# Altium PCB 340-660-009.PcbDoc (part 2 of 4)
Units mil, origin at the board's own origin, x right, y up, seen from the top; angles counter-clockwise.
Board outline 2755.91 x 2755.91 mil, 4 copper layers (Top Layer, Int1 (PWR), Int2 (GND), Bottom Layer), stack 53.912 mil thick; 183 components, 253 nets, 930 pads, 492 vias.
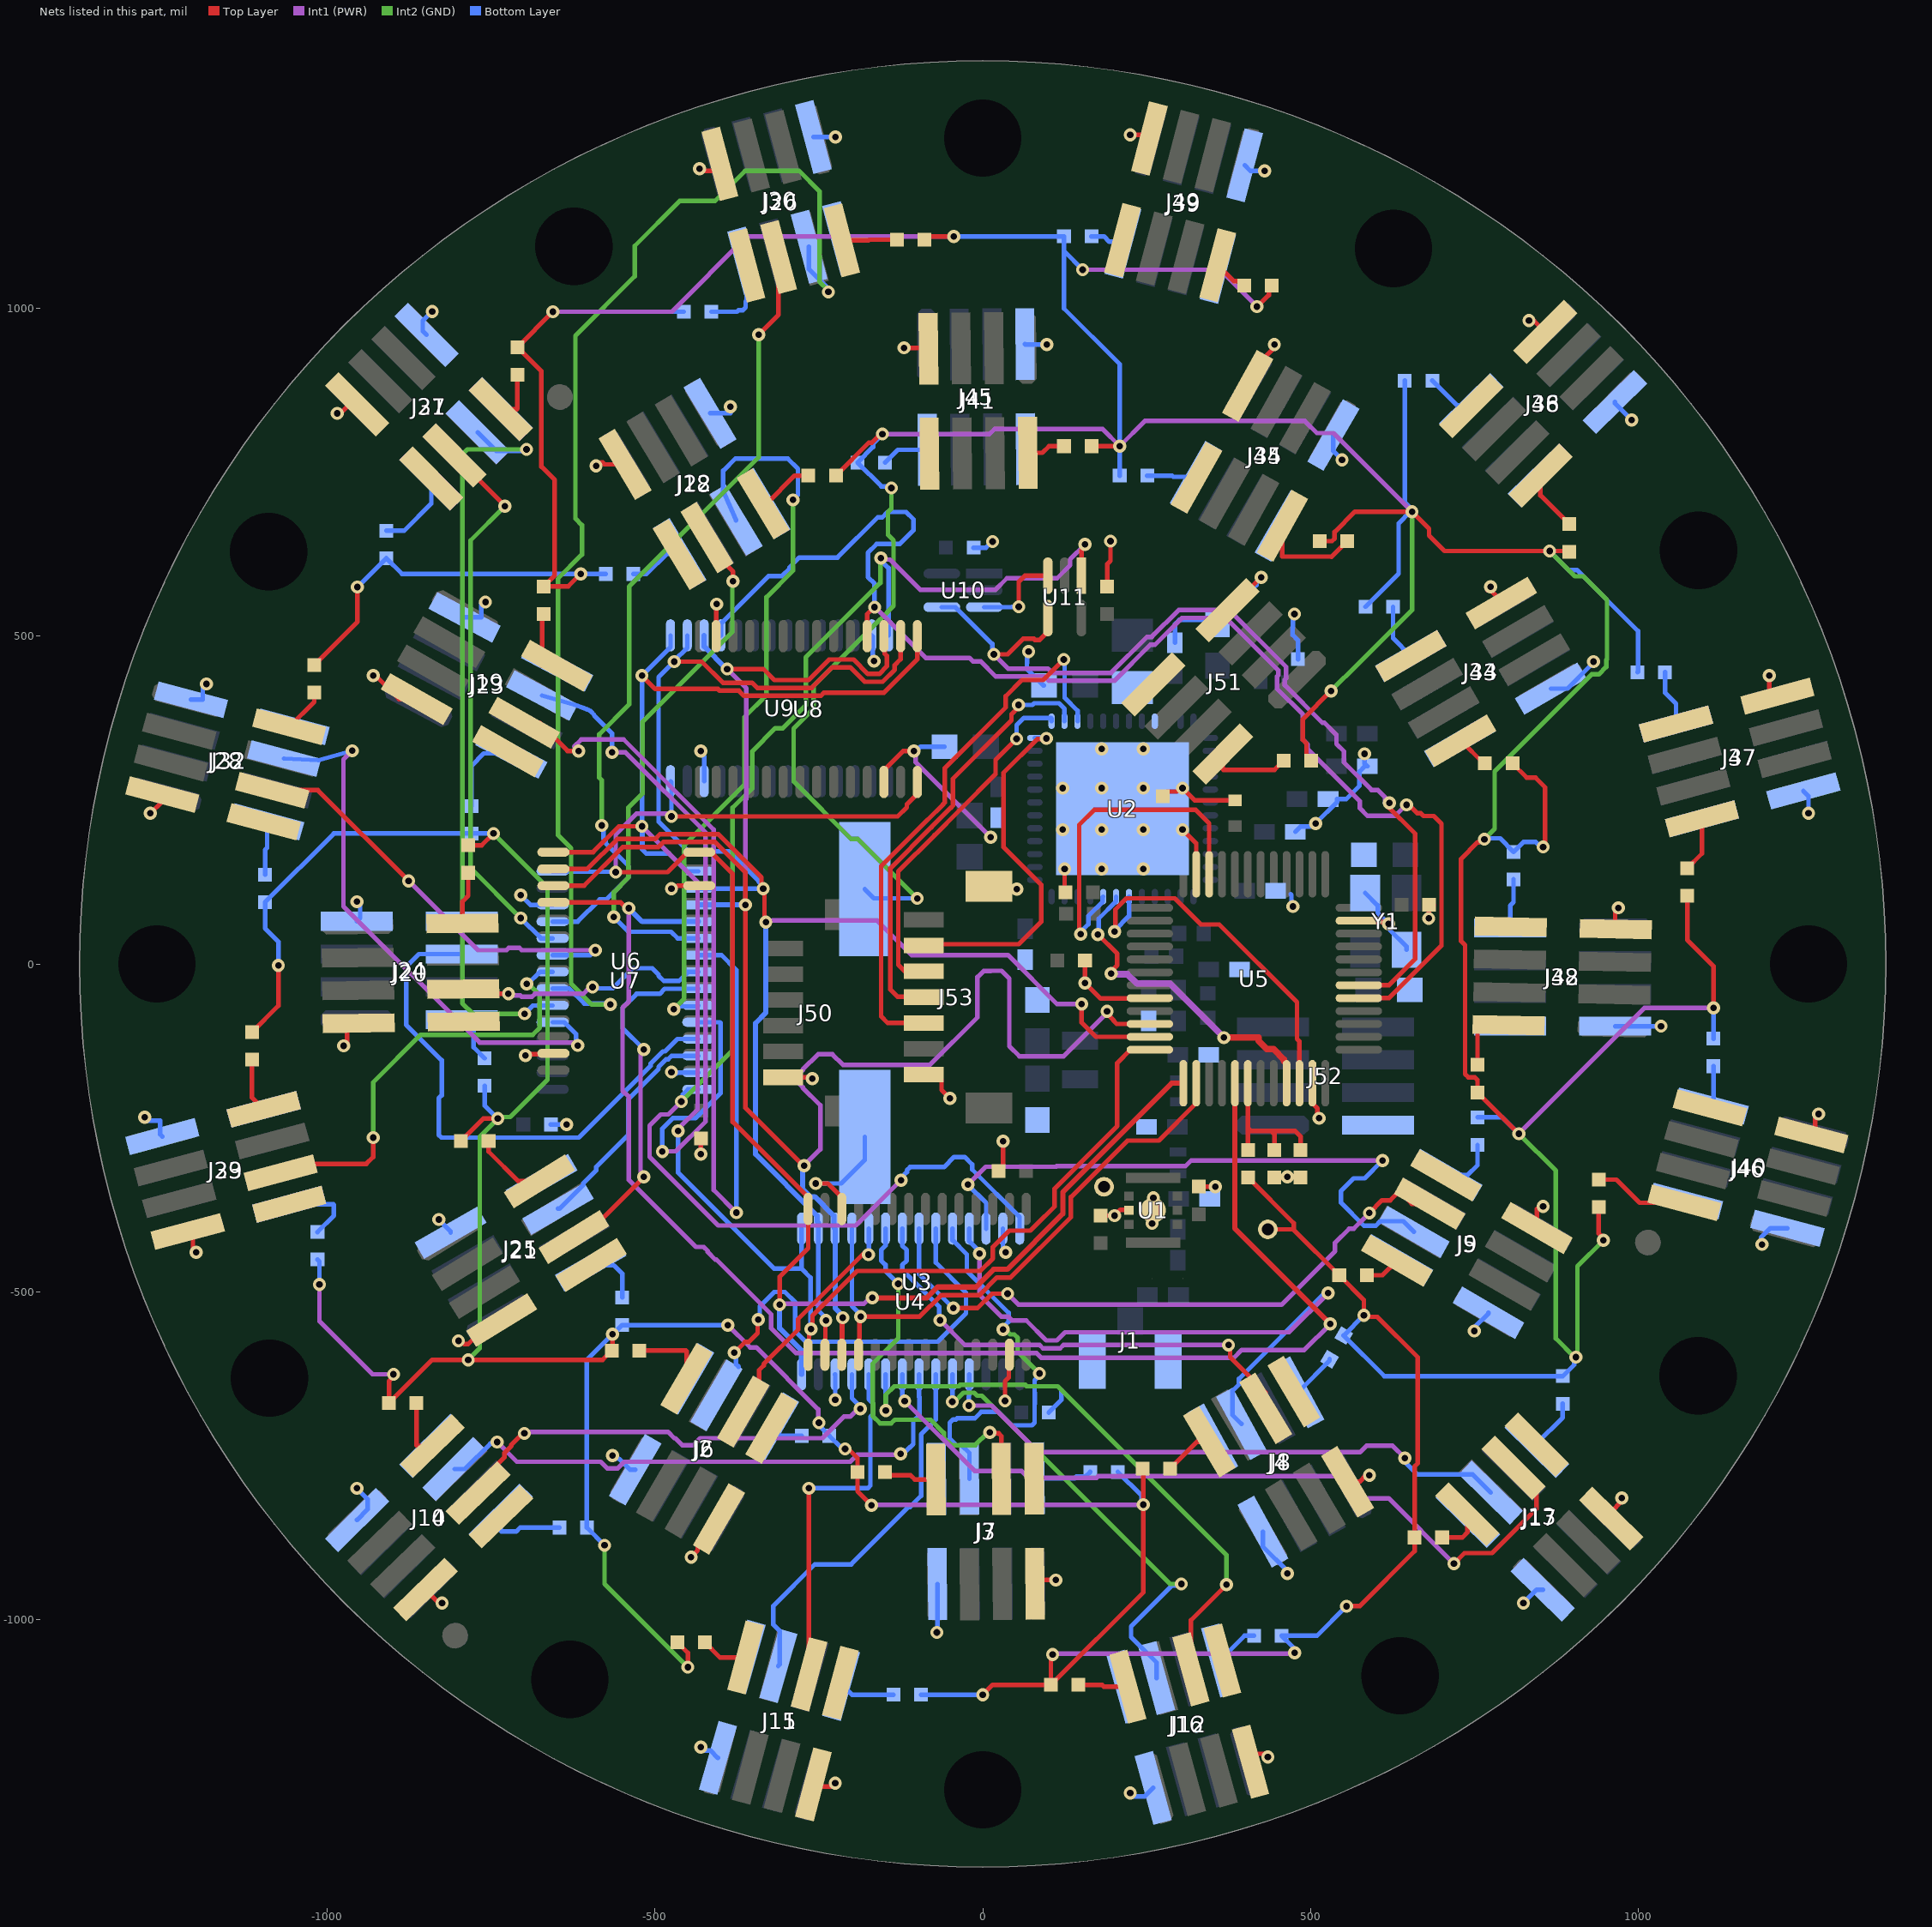
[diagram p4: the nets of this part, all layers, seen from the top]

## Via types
v1: diameter 20, hole 10, Top Layer to Bottom Layer, tented both sides, 489 vias
v2: diameter 20, hole 10, Top Layer to Bottom Layer, 3 vias

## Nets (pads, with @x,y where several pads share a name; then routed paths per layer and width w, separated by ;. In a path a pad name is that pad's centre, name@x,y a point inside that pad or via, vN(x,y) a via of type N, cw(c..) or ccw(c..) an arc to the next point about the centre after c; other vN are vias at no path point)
CTR_A0: U3.17 U4.17 U5.10 U6.17 U7.17 U8.17 U9.17 | length 2948.7
  Top Layer w7: U6.17@-655,119.41 -608.17,119.41 -549.08,178.5 -494.84,178.5 -487.37,185.98 -408.47,185.98 -362.04,139.55 -362.04,-219.54 -273.93,-307.65 v1(-272.65,-307.65) ; v1(-390,450) -334.63,450 -317.72,433.08 -265.87,433.08 -234.38,464.58 -197.14,464.58 -175.09,442.52 -157.73,442.52 -146.31,453.94 -146.31,470.1 -149.57,473.36 -149.57,498.7 U8.17@-150.87,500 ; v1(189.79,-72.26) 189.79,-75.78 199.5,-85.48 199.5,-86.59 204.45,-91.54 U5.10@254.94,-91.54
  Top Layer w8: U3.17@-215.16,-596.22 -214.4,-595.46 -214.4,-540.56 v1(-213.64,-539.8)
  Int1 (PWR) w7: v1(-390,450) -360.6,420.6 -360.6,251.58 -362.04,250.14 v1(-362.04,90.16) ; v1(-272.65,-307.65) -247.81,-282.81 -247.81,-215.6 -274.5,-188.9 -274.5,-188.08 -279.5,-183.08 -279.5,-166.92 -274.5,-161.92 -274.5,-161.1 -251.16,-137.76 -229.5,-137.76 -213.3,-153.96 -80.48,-153.96 -8,-81.48 -8,-20.17 1.29,-10.87 12.17,-10.87 12.54,-10.5 28.69,-10.5 40.5,-22.31 40.5,-125.41 55.91,-140.82 123.53,-140.82 189.79,-74.56 v1(189.79,-72.26)
  Bottom Layer w8: U7.17@-433.78,90.16 v1(-362.04,90.16) ; U9.17@-425.16,501.22 -425.16,484.33 -390.83,450 v1(-390,450) ; v1(-272.65,-307.65) -274.95,-309.95 -274.95,-326.66 -275,-326.72 -275,-343.28 -263.28,-355 -256.22,-355 -227.05,-384.18 -227.05,-401.89 U4.17@-225.16,-403.78 -225.16,-525.03 -213.64,-536.55 v1(-213.64,-539.8)
CTR_A1: U3.16 U4.16 U5.11 U6.16 U7.16 U8.16 U9.16 | length 2869.2
  Top Layer w7: U6.16@-655,145 -603.14,145 -557.64,190.5 -499.82,190.5 -492.34,197.98 -403.5,197.98 -337.49,131.97 -337.49,115.5 -332.97,110.98 -332.97,65.66 v1(-330.94,63.63) ; v1(-470.81,461.29) -428.87,461.29 -396.55,428.97 -351.88,428.97 -343.99,421.08 -260.9,421.08 -229.41,452.58 -202.11,452.58 -180.06,430.52 -152.76,430.52 -134.31,448.97 -134.31,455.86 -125.28,464.89 U8.16@-125.28,500 ; U3.16@-240.75,-596.22 -240.03,-595.5 -240.03,-544.58 v1(-239.32,-543.86) ; v1(151,-61.22) 151,-89.38 172.85,-111.23 U5.11@254.94,-111.23
  Int1 (PWR) w7: v1(-330.94,63.63) -328.45,66.12 -320.6,66.12 -320.34,66.38 -161.38,66.38 -108.5,13.5 38.64,13.5 113.35,-61.22 v1(151,-61.22)
  Bottom Layer w7: U9.16@-450.75,501.22 -450.75,482.43 -470.81,462.37 v1(-470.81,461.29) -494.5,437.6 -494.5,216.92 -449.53,171.96 -387.07,171.96 -342.1,126.99 -342.1,125.62 v1@-333.24,116.76 ; U7.16@-433.78,115.75 -433.03,115 v1(-335,115) ; U4.16@-250.75,-394.92 -250.75,-528.92 -239.32,-540.35 v1(-239.32,-543.86)
  Bottom Layer w8: v1(-330.94,63.63) -330.94,-74.55 -346.65,-90.26 -346.65,-290.16 -252.64,-384.18 -252.64,-393.03 U4.16@-250.75,-394.92
CTR_A2: U3.15 U4.15 U5.12 U6.15 U7.15 U8.15 U9.15 | length 2937.3
  Top Layer w7: U6.15@-655,170.59 -594.52,170.59 -555.11,210 v1(-520,210) ; v1(-520,439.84) -499.66,419.5 -404.05,419.5 -401.52,416.97 -372.02,416.97 -364.13,409.08 -246.99,409.08 -242.5,413.58 -151,413.58 -99.68,464.89 U8.15@-99.68,500 ; U3.15@-266.34,-596.22 -265.04,-594.92 -265.04,-563.33 -259.68,-557.97 -259.68,-536.65 -191.53,-468.5 -3.61,-468.5 15.5,-449.39 15.5,-431.92 40.54,-406.89 72.71,-406.89 81.73,-397.87 109.66,-369.94 109.66,-342.98 205.26,-247.38 205.26,-151.07 225.41,-130.92 U5.12@254.94,-130.92
  Int1 (PWR) w7: v1(-520,210) -435,125 -435,-222.12 -465,-252.12 v1(-465,-255)
  Bottom Layer w7: v1(-520,210) -520,175 -517.5,172.5 ; U9.15@-476.34,501.22 -476.34,483.5 v1(-520,439.84) -520,208.75 -518.75,207.5 -518.75,173.75 -517.5,172.5 ; v1(-465,-255) -465,-318.08 -318.08,-465 -276.34,-465 ; U7.15@-433.78,141.34 -451.5,141.34 -478.66,168.5 -513.5,168.5 -517.5,172.5 ; U4.15@-276.34,-403.78 -276.34,-465 ; v1(-262.16,-556.94) -262.75,-556.36 -262.75,-478.59 -276.34,-465
CTR_A3: U3.14 U4.14 U5.13 U6.14 U7.14 U8.14 U9.14 | length 2542.6
  Top Layer w7: v1(-560,140) -480.87,140 -450.28,170.59 -414.84,170.59 -381.54,137.28 -381.54,-240.87 -266.34,-356.06 -266.34,-433.72 -310,-477.39 v1(-310,-520) ; v1(-475,225) -129.85,225 -115.88,238.98 -115.88,243.65 -99.68,259.84 U8.14@-99.68,277.56
  Top Layer w8: v1(-168.63,-509.44) -85.34,-509.44 -68.9,-493 -10.44,-493 16.59,-465.97 37.31,-465.97 122.16,-381.13 122.16,-348.16 288.22,-182.1 U5.13@306.12,-182.1
  Int1 (PWR) w7: v1(-560,140) -560,197.58 -528.08,229.5 -483.02,229.5 -478.52,225 v1(-475,225) ; v1(-310,-520) -308.44,-518.44 -181.15,-518.44 -172.15,-509.44 v1(-168.63,-509.44)
  Bottom Layer w7: U7.14@-656.22,141.34 -655.55,140.67 -560.67,140.67 v1(-560,140) ; U9.14@-476.34,278.78 -475.04,277.48 -475.04,254.97 -475,254.93 v1(-475,225)
  Bottom Layer w8: v1(-310,-520) -310,-555.95 -276.34,-589.61 U4.14@-276.34,-626.22
CTR_A4: U3.18 U4.18 U5.14 | length 894.4
  Top Layer w7: U3.18@-189.57,-596.22 -188.27,-594.92 -188.27,-539.86 v1(-186.35,-537.94) -96.17,-537.94 -63.72,-505.5 -5.26,-505.5 21.77,-478.47 42.49,-478.47 134.66,-386.3 134.66,-355.7 220.85,-269.5 268.62,-269.5 325.81,-212.31 U5.14@325.81,-182.1
  Bottom Layer w7: U4.18@-199.57,-403.78 -199.57,-522.16 -186.35,-535.38 v1(-186.35,-537.94)
CTR_A5: U5.17 U6.18 U7.18 | length 2300.8
  Top Layer w7: U6.18@-655,93.82 -552.34,93.82 -543.52,85 v1(-540,85)
  Top Layer w8: U5.17@384.86,-182.1 384.86,-403.76 v1(530.4,-549.3)
  Int1 (PWR) w7: v1(-540,85) -540,-57.42 -549.5,-66.92 -549.5,-193.5 -540,-203 -540,-329.58 -437.75,-431.83 -425.75,-431.83 -419.53,-438.05 -419.53,-439.62 -408.11,-451.05 -406.53,-451.05 -322.71,-534.86 -322.71,-556.03 -285.24,-593.5 81.98,-593.5 89.48,-601 383.08,-601 395.08,-589 490.7,-589 v1(530.4,-549.3)
  Bottom Layer w8: v1(-540,85) -519.57,64.57 U7.18@-433.78,64.57
CTR_A6: U5.29 U8.18 U9.18 | length 2117.5
  Top Layer w7: U8.18@-176.46,500 -176.46,533.54 -165.61,544.39 v1(-165,544.39) ; U5.29@573.84,-52.17 619.8,-52.17 700,28.03 700,213.75 688.12,225.63 672.77,225.63 668.22,230.17 662.71,230.17 650.26,242.63 v1(646.74,242.63)
  Int1 (PWR) w7: v1(-165,544.39) -164.39,544.39 -86.94,466.94 -20.42,466.94 -15.13,461.65 -3.1,461.65 19.98,438.57 94.46,438.57 101.09,431.94 200.72,431.94 255.82,487.04 262.99,487.04 303.95,528 371.09,528 451,448.09 451,440.52 449,438.52 449,420.13 488.5,380.64 488.5,342.45 496,334.95 496,327.7 575.2,248.5 575.2,237.89 587.1,225.99 629.43,225.99 646.07,242.63 v1(646.74,242.63)
  Bottom Layer w7: U9.18@-399.57,501.22 -399.57,518.94 -326.68,591.82 -306.18,591.82 -294.76,603.25 -294.76,605.24 -280,620 -221.68,620 -160.29,681.39 -153.2,681.39 -145.09,689.5 -116.92,689.5 -105.5,678.08 -105.5,661.92 -126.78,640.64 -161.89,640.64 -175.06,627.47 -175.06,590.24 -165,580.19 v1(-165,544.39)
CTR_A7: U5.30 U10.4 U11.4 | length 1415.4
  Top Layer w7: v1(17.03,472.32) 38.22,472.32 60.4,494.5 61.92,496 78.08,496 79.62,494.45 86.75,494.45 99.41,507.11 U11.4@99.41,527.71 ; U5.30@573.84,-32.49 619.77,-32.49 660,7.74 660,198.57 616.98,241.58 620.7,245.3 v1(620.7,245.49)
  Int1 (PWR) w7: v1(17.03,472.32) 38.79,450.57 99.43,450.57 106.06,443.94 195.75,443.94 250.85,499.04 258.02,499.04 298.98,540 376.06,540 463,453.06 463,435.55 461,433.55 461,425.1 518.1,368 521.37,368 539.82,349.55 539.82,335.67 551.16,324.33 551.16,307.43 593.13,265.47 602.78,265.47 614.2,254.04 614.2,245.46 614.37,245.3 620.7,245.3 v1(620.7,245.49)
  Bottom Layer w7: U10.4@-62.29,544.41 -41.69,544.41 14.54,488.18 14.54,474.81 v1(17.03,472.32)
DCDC_SW: L2.1 U2.33
DIO1: U2.6 U5.22 | length 571.3
  Top Layer w7: v1(201.31,49.46) 202.47,50.62 202.47,83.05 219.45,100.03 293,100.03 332.76,60.27 360.82,60.27 479.5,-58.41 479.5,-114.5 483.29,-118.29 U5.22@483.29,-182.1
  Bottom Layer w7: v1(201.31,49.46) 201.31,51.26 223.21,73.15 U2.6@223.21,102.68
DIO2: U2.7 U5.21 | length 503.9
  Top Layer w7: v1(175.64,45) 205.2,15.43 205.2,-1.97 195.99,-11.18 v1(195.99,-14.7)
  Top Layer w10: v1(368.03,-112.41) 421.2,-112.41 421.2,-117.59 433.5,-129.89 443.73,-129.89 459.82,-145.98 459.82,-148.3 463.6,-152.08 U5.21@463.6,-182.1
  Int1 (PWR) w10: v1(195.99,-14.7) 197.07,-15.78 220.99,-15.78 235.2,-30 285.62,-30 v1(368.03,-112.41)
  Bottom Layer w7: v1(175.64,45) 176.93,46.3 176.93,69 203.52,95.59 U2.7@203.52,102.68
DIO3: U2.8 U5.46 | length 532.9
  Top Layer w7: v1(149.64,45.5) 147.27,47.87 147.27,212.27 170,235 325,235 345.49,214.51 U5.46@345.49,136.8
  Bottom Layer w7: v1(149.64,45.5) 149.64,49.02 161.29,60.66 161.29,73.04 183.04,94.79 183.04,101.88 U2.8@183.84,102.68
ENB_1: J2.8
ENB_2: J3.8
ENB_3: J4.8
ENB_4: J5.8
ENB_5: J6.8
ENB_6: J7.8
ENB_7: J8.8
ENB_8: J9.8
ENB_9: J10.8
ENB_10: J11.8
ENB_11: J12.8
ENB_12: J13.8
ENB_13: J14.8
ENB_14: J15.8
ENB_15: J16.8
ENB_16: J17.8
ENB_17: J18.8
ENB_18: J19.8
ENB_19: J20.8
ENB_20: J21.8
ENB_21: J22.8
ENB_22: J23.8
ENB_23: J24.8
ENB_24: J25.8
ENB_25: J26.8
ENB_26: J27.8
ENB_27: J28.8
ENB_28: J29.8
ENB_29: J30.8
ENB_30: J31.8
ENB_31: J32.8
ENB_32: J33.8
ENB_33: J34.8
ENB_34: J35.8
ENB_35: J36.8
ENB_36: J37.8
ENB_37: J38.8
ENB_38: J39.8
ENB_39: J40.8
ENB_40: J41.8
ENB_41: J42.8
ENB_42: J43.8
ENB_43: J44.8
ENB_44: J45.8
ENB_45: J46.8
ENB_46: J47.8
ENB_47: J48.8
ENB_48: J49.8
ENB_49: J51.8
ENBL_TIA: U4.28 U7.28 U9.28 U11.1 | length 2365.6
  Top Layer w7: U11.1@150.59,592.29 150.59,631.07 156,636.48 v1(156,640)
  Int1 (PWR) w7: v1(-460,-210) -479.59,-229.59 -491.23,-229.59 -508.33,-246.69 -508.33,-294.4 -403.73,-399 -193.63,-399 v1(-124.63,-330) ; v1(-155.56,619.39) -153.07,616.91 -141.45,616.91 -95.54,571 19.48,571 36.98,588.5 113.5,588.5 133.51,608.51 133.51,617.51 v1(156,640)
  Int2 (GND) w7: v1(-460,-210) -381.54,-131.54 -381.54,238.46 -351.5,268.5 -351.5,324.58 -316.46,359.61 -305.04,359.61 -270,394.65 -270,467.58 -156.16,581.42 -156.16,618.79 v1(-155.56,619.39)
  Bottom Layer w7: v1(-460,-210) -457.51,-207.51 -457.51,-199.19 -449.66,-191.34 U7.28@-433.78,-191.34 ; v1(-155.56,619.39) -155.56,615.88 -143.66,603.98 U9.28@-143.66,501.22 ; v1(-124.63,-330) -124.63,-326.48 -115.64,-317.49 -115.64,-314.95 -110.69,-310 -58.97,-310 -43.58,-294.61 -27.42,-294.61 -16,-306.03 -16,-313.72 56.34,-386.06 U4.28@56.34,-403.78
GND: C1.1 C2.1 C3.- C5.2 C6.2 C7.2 C8.2 C9.2 C10.2 C11.2 C12.2 C14.1 C16.2 C17.2 C18.2 C20.1 C21.1 C22.2 C23.2 C24.2 C25.1 C26.1 C27.1 C28.1 C29.1 C30.1 C31.1 C32.1 C33.1 C34.1 C35.1 C36.1 C37.1 J1.1 J1.2 J2.7 J3.7 J4.7 J5.7 J6.7 J7.7 J8.7 J9.7 J10.7 J11.7 J12.7 J13.7 J14.7 J15.7 J16.7 J17.7 J18.7 J19.7 J20.7 J21.7 J22.7 J23.7 J24.7 J25.7 J26.7 J27.7 J28.7 J29.7 J30.7 J31.7 J32.7 J33.7 J34.7 J35.7 J36.7 J37.7 J38.7 J39.7 J40.7 J41.7 J42.7 J43.7 J44.7 J45.7 J46.7 J47.7 J48.7 J49.7 J50.6 J51.7 J52.2 J53.7 J53.9 R2.1 R53.2 R55.1 TP2.1 U1.2 U1.9 U2.49 U3.12 U3.27 U4.12 U4.27 U5.8 U5.23 U5.35 U5.47 U6.12 U6.27 U7.12 U7.27 U8.12 U8.27 U9.12 U9.27 U10.3 U11.3 Y1.2 Y1.4 | length 5035.8
  Top Layer w7: v1(-1270,230) -1251.78,248.22 J28.7@-1251.78,258.25 ; J29.7@-1212.96,-408.19 -1205,-416.15 -1205,-435.9 -1200.9,-440 v1(-1200,-440) ; v1(-985,840) -980,840 -966.25,853.75 J27.7@-954.68,853.75 ; v1(-975,-125) -974.1,-125 -970,-120.9 -970,-102.27 -958.18,-90.45 J20.7@-952.1,-90.45 ; v1(-930,439.96) -926.48,439.96 -890.62,404.1 J19.7@-863.6,404.1 ; J10.7@-850.41,-954.61 -830.02,-975 v1(-825,-975) ; v1(-800,-575) -796.48,-575 -791.48,-580 -785,-580 -748.33,-543.33 J21.7@-733.93,-543.33 ; v1(-697.79,-139.5) -696.08,-137.79 -656.3,-137.79 U6.27@-655,-136.5 ; v1(-590,760) -587.91,760 -582.73,765.18 -580.18,765.18 -577.14,762.14 J18.7@-545.86,762.14 ; v1(-475,115) -470,115 -465.59,119.41 U6.12@-432.56,119.41 ; v1(-445,-905) -435,-895 -435,-890 -402.39,-857.39 J2.7@-402.39,-846.78 ; v1(-432.17,1213.08) -429.09,1210 -411.55,1210 J26.7@-400.92,1220.63 ; v1(-430,-290) C33.1@-430,-266 ; U8.27@-406.77,500 -406.77,548.17 v1(-405.94,549) ; J50.6@-304.41,-173.03 -261.97,-173.03 v1(-260,-175) ; J11.7@-258.12,-1251.71 -254.83,-1255 -229.1,-1255 -225,-1250.9 v1(-225,-1250) ; v1(-255,-335) -236.22,-335 -215.16,-356.06 U3.12@-215.16,-373.78 ; U8.12@-150.87,277.56 -150.87,295.28 -121.14,325 v1(-105,325) ; v1(-120,940) -84.15,940 J41.7@-82.74,938.6 ; J53.7@-89.88,-168.81 -71.18,-168.81 -62.87,-177.12 -62.87,-192.13 v2(-50,-205) ; C31.1@24,-316.27 31,-309.27 v2(31,-270.5) ; v1@35,-660 35,-665.65 v1(34.06,-666.58) 34.06,-636.84 40,-630.9 40,-596.97 U3.27@40.75,-596.22 ; v1(55,545) 55,583.19 64.1,592.29 U11.3@99.41,592.29 ; J3.7@79.62,-945.76 85.38,-940 v1(111.37,-939.99) ; C27.1@124.4,115.43 125,116.03 v1(125,145) ; C29.1@156,5 156,-29.08 v1(156.17,-29.25) 156.57,-29.25 180.08,-52.76 254.36,-52.76 U5.8@254.94,-52.17 ; C1.1@180,-384 v1(201,-384) 210,-375 222.3,-375 U1.2@223.09,-375.79 ; C36.1@190,576 190,607.1 190,610 195,615 v1(195,645) ; v1(225,1265) 248.63,1265 J49.7@254.3,1259.34 ; C26.1@275,256 282,263 296.21,263 301.38,268.17 v1(304.9,268.17) 323.39,249.69 R53.2@385,249.69 ; v1(304.9,204.9) 325.81,184 U5.47@325.81,136.8 ; C2.1@332.26,-340 v1(355,-340) ; J51.7@373.62,539.69 410.51,575.51 v1(424.76,589.76) ; J35.7@404.35,881.78 404.35,899.35 445,940 v1(445,945) ; J12.7@408.68,-1217.16 420.84,-1205 430.9,-1205 435,-1209.1 v1(435,-1210) ; R55.1@445,-326 464,-326 v1(465,-325) 484,-325 C30.1@485,-326 ; U5.23@502.97,-182.1 502.97,-212.93 510.73,-220.68 510.73,-232.93 v1(513.21,-235.42) ; J4.7@556.58,-790.11 574.89,-790.11 585,-780 v1(590,-780) ; U5.35@573.84,65.94 574.76,65.02 608.09,65.02 609.29,63.82 616.76,63.82 v1(619.25,61.34) ; v1(680.5,69.49) 680.5,83 687.5,90 C28.1@688,90 ; v1@770,570 774.76,574.76 v1(774.76,575.42) 774.76,570.24 791.36,553.64 J34.7@791.36,550.74 ; v1(833.41,981.62) 833.49,981.71 840.88,981.71 J48.7@858.25,964.34 ; J5.7@845.68,-402.84 845.68,-374.1 850.9,-374.1 v1(855,-370) ; J13.7@958.91,-846.31 958.91,-836.09 975,-820 v1(975,-815) ; J38.7@965.9,53.15 965,54.06 965,81.18 969.38,85.57 v1(970,85.57) ; v1(1200,440) 1200,421 J47.7@1212.58,408.43 ; J46.7@1264.31,-261.19 1270,-255.5 1270,-234.1 1275.12,-228.98 v1(1275.27,-228.98)
  Int1 (PWR) w7: v1(-105,325) -102.51,322.51 -102.51,307.88 v1(12.18,193.19)
  Bottom Layer w7: v1(-1278.5,-233.93) -1278.5,-234.59 -1273.99,-239.1 -1255,-239.1 -1255,-260.09 J33.7@-1251.8,-263.29 ; J32.7@-1208.01,403.16 -1190,403.16 -1190,430 -1185,430 -1185,427.73 v1(-1184.42,427.15) ; J24.7@-955.12,65 -950,70.12 -950,90.9 -954.1,95 v1(-955,95) ; v1(-955,-800) -938.57,-816.43 -938.57,-832.25 J14.7@-954.69,-848.38 ; J31.7@-848.62,959.69 -854.39,965.46 -854.39,981.11 v1(-840,995.5) ; v1(-830,-390) -811.88,-408.12 J25.7@-811.88,-410.11 ; J23.7@-790.55,528.83 -765,528.83 -765,550 -760,550 -760,550.93 v1(-758.76,552.17) ; v1(-705,105) -690.16,90.16 U7.12@-656.22,90.16 ; C34.1@-659,-245 v1(-635,-245) ; v1(-565,-750) -561.48,-750 -556.48,-755 -555,-755 -538.44,-771.56 J6.7@-530.11,-771.56 ; v1(-475,-165) -472.9,-167.1 -467.1,-167.1 -465.75,-165.75 U7.27@-433.78,-165.75 ; v1(-430,-1195) -430,-1200 -415.53,-1200 J15.7@-404.16,-1211.37 ; v1(-430,325) -430,321.48 -425,316.48 -425,278.94 U9.12@-425.16,278.78 ; J22.7@-415.91,840.15 -385,840.15 v1(-385,850) ; J30.7@-258.29,1261.8 -220,1261.8 -220,1260 -222.83,1260 v1(-224.59,1261.76) ; v1(-255,-335) -215.87,-335 -180,-299.13 C3.-@-180,-263.98 ; U4.12@-225.16,-626.22 -225,-626.38 v1(-225,-665) ; U9.27@-169.25,501.22 -167.95,499.92 -167.95,464.17 v1(-165.81,462.02) ; v1(-105,325) -101.48,325 -94.95,331.54 C21.1@-58.13,331.54 ; v1(-70,-1020) -69.16,-1019.16 J7.7@-69.16,-946.13 ; C35.1@-14,635 4.89,635 14.39,644.5 v1(15,644.5) ; U10.3@2.29,544.41 44.41,544.41 45,545 v1(55,545) ; U4.27@30.75,-403.78 30.75,-435.9 34.85,-440 v1(35,-440) ; J45.7@64.5,945.59 65.08,945 v1@97.75,945 ; v1(70,476.5) 67.51,474.01 67.51,459.59 67.42,459.5 67.42,450.1 92.52,425 C10.2@93.5,425 ; C32.1@100.76,-684.47 120,-665.23 120,-650 ; v1(225,-1265) 225,-1265.9 229.1,-1270 247.2,-1270 J16.7@259.95,-1257.25 ; C9.2@293.37,490.16 293.37,518.37 300,525 343.17,525 C8.2@358.37,518.03 ; C8.2@358.37,519.02 417.51,578.16 417.51,582.51 v1(424.76,589.76) ; J39.7@399.65,1218.6 408.25,1210 v1(430,1210) ; J8.7@427.55,-866.26 427.55,-889.03 465,-926.48 v1(465,-930) ; 469.74,106.54 470.96,105.32 470.96,90.19 v1(473.44,87.7) ; v1(475.69,533.86) 473.21,531.37 473.21,513.85 472.9,513.55 472.9,502.1 481,494 C20.1@481,465 ; C11.2@476.99,201.54 485.3,209.85 500,209.85 504.53,214.38 v1(508.05,214.38) 540.82,247.15 540.82,251.54 554.64,251.54 574.74,271.63 574.74,293.22 583.05,301.54 R2.1@586.99,301.54 582.66,305.86 v1(582.66,320.48) ; J44.7@535.01,806.88 535.01,782.41 v1(548.27,769.15) ; Y1.2@583.5,108.31 602.64,89.17 602.64,77.94 621.74,58.85 621.74,51.37 646.5,26.61 Y1.4@646.5,21.69 ; v1(750,-560) 750,-555 771.76,-533.24 J9.7@771.76,-532.18 ; v1(825,-975) 845.35,-954.65 J17.7@854.56,-954.65 ; J43.7@866.88,420.11 892.31,420.11 927.2,455 927.83,455 931.93,459.1 v1(931.93,461.23) 930.7,460 v1@930,460 ; J36.7@964.72,857.48 964.72,855.28 v1(990,830) ; J42.7@965.12,-95 v1(1035,-95) ; v1(1189.2,-427.98) 1187.5,-426.27 1187.5,-417.5 1201.78,-403.22 J40.7@1227.91,-403.22 ; J37.7@1252.13,263.92 1260,256.05 v1(1260,230)
  other v1: 258.5,-395.94 260.38,-356.92 52.02,114.03 181.73,145 245,145 121.83,204.9 181.73,204.9 245,204.9 121.83,268.17 181.73,268.17 245,268.17 181.73,328.07 245,328.07 97.77,945.03
HARV_1: J2.2 R4.1 | length 114.4
  Top Layer w7: R4.1@-524,-590 -452.93,-590 -451.93,-591 J2.2@-451.93,-632.96
HARV_2: J3.2 R5.1 | length 82.3
  Top Layer w7: R5.1@-149,-775 -143.78,-780.22 -110.13,-780.22 -103.73,-786.62 J3.2@-71.54,-786.62
HARV_3: J4.2 R6.1 | length 76.7
  Top Layer w7: R6.1@286,-770 326.94,-729.06 J4.2@345.75,-729.06
HARV_4: J5.2 R7.1 | length 55.5
  Top Layer w7: R7.1@586,-475 610,-475 631.9,-453.1 J5.2@631.9,-452.56
HARV_5: J6.2 R8.1 | length 48.7
  Bottom Layer w7: J6.2@-319.89,-708.44 -308.33,-720 R8.1@-276,-720
HARV_6: J7.2 R9.1 | length 88.4
  Bottom Layer w7: J7.2@79.67,-784.8 140.27,-784.8 143.08,-782 157,-782 R9.1@164,-775
HARV_7: J8.2 R10.1 | length 70.1
  Bottom Layer w7: J8.2@482.45,-653.74 482.45,-652 529.27,-605.18 R10.1@529.27,-603.05
HARV_8: J9.2 R11.1 | length 84.4
  Bottom Layer w7: J9.2@707.99,-322.15 740,-322.15 755,-307.15 R11.1@755,-276
HARV_9: J10.2 R12.1 | length 89.2
  Top Layer w7: R12.1@-864,-670 -864,-734.39 -863,-735.39 J10.2@-839.6,-735.39
HARV_10: J11.2 R13.1 | length 71.8
  Top Layer w7: R13.1@-424,-1035 -400.71,-1058.29 J11.2@-361.87,-1058.29
HARV_11: J12.2 R14.1 | length 76.5
  Top Layer w7: R14.1@146,-1100 182,-1100 184.84,-1102.84 J12.2@221.32,-1102.84
HARV_12: J13.2 R15.1 | length 69.3
  Top Layer w7: R15.1@701,-875 732,-875 739.52,-867.48 J13.2@739.52,-839.79
HARV_13: J14.2 R16.1 | length 115.6
  Bottom Layer w7: J14.2@-735.31,-841.62 -735.31,-865 -734.31,-866 -712,-866 -706,-860 R16.1@-646,-860
HARV_14: J15.2 R17.1 | length 86.6
  Bottom Layer w7: J15.2@-215.84,-1098.63 -199.47,-1115 R17.1@-136,-1115
HARV_15: J16.2 R18.1 | length 68
  Bottom Layer w7: J16.2@361.68,-1062.75 399.43,-1025 R18.1@414,-1025
HARV_16: J17.2 R19.1 | length 80.7
  Bottom Layer w7: J17.2@845.44,-735.35 845.44,-731.56 885,-692 R19.1@885,-671
HARV_17: J18.2 R20.1 | length 86.5
  Top Layer w7: J18.2@-334.75,702.05 -329.95,702.05 -287,745 R20.1@-266,745
HARV_18: J19.2 R21.1 | length 103.3
  Top Layer w7: R21.1@-670,534 -670,531.61 -672.11,531.61 -672.11,454.9 J19.2@-650.07,454.9
HARV_19: J20.2 R22.1 | length 81
  Top Layer w7: J20.2@-793.95,61.75 -793.95,95 -785,103.95 R22.1@-785,139
HARV_20: J21.2 R23.1 | length 112.7
  Top Layer w7: R23.1@-754,-270 -754,-286.19 -708.65,-331.54 J21.2@-676.29,-331.54
HARV_21: J22.2 R24.1 | length 83.4
  Bottom Layer w7: R24.1@-533,595 -513,595 -482.4,625.6 J22.2@-462.24,625.6
HARV_22: J23.2 R25.1 | length 129.8
  Bottom Layer w7: R25.1@-780,241 -780,302.5 -761.33,321.17 J23.2@-719.45,321.17
HARV_23: J24.2 R26.1 | length 77.5
  Bottom Layer w7: J24.2@-794.88,-85 -787.97,-85 -776.9,-96.07 -776.9,-127.1 R26.1@-760,-144
HARV_24: J25.2 R27.1 | length 89.8
  Bottom Layer w7: J25.2@-598.12,-459.89 -562.61,-459.89 -550,-472.5 R27.1@-550,-509
HARV_25: J26.2 R28.1 | length 84.3
  Top Layer w7: J26.2@-214.9,1104.14 -174,1104.14 -173.14,1105 R28.1@-131,1105
HARV_26: J27.2 R29.1 | length 77.5
  Top Layer w7: J27.2@-735.32,846.24 -711,846.24 -710,847.24 R29.1@-710,899
HARV_27: J28.2 R30.1 | length 68.1
  Top Layer w7: J28.2@-1058.22,361.75 -1020,399.97 R30.1@-1020,414
HARV_28: J29.2 R31.1 | length 83.3
  Top Layer w7: R31.1@-1115,-146 -1115,-203.85 J29.2@-1097.04,-221.81
HARV_29: J30.2 R32.1 | length 123
  Bottom Layer w7: R32.1@-414,995 -375.09,995 -372.6,997.48 -365.81,997.48 -361.71,1001.58 -361.71,1010.78 -360.11,1012.37 -360.11,1066.61 J30.2@-361.71,1068.2
HARV_30: J31.2 R33.1 | length 123.6
  Bottom Layer w7: R33.1@-910,661 -882.88,661 -841.38,702.5 J31.2@-841.38,740.31
HARV_31: J32.2 R34.1 | length 82.1
  Bottom Layer w7: R34.1@-1095,136 -1095,174 -1091.99,177.01 J32.2@-1091.99,216.84
HARV_32: J33.2 R35.1 | length 120.3
  Bottom Layer w7: J33.2@-1058.2,-366.71 -991,-366.71 -990,-367.71 -990,-384 R35.1@-1015,-409
HARV_33: J34.2 R36.1 | length 51.6
  Top Layer w7: J34.2@728.95,340.31 730,340.31 764.43,305.88 R36.1@766.33,305.88
HARV_34: J35.2 R37.1 | length 155.5
  Top Layer w7: J35.2@457.16,668.74 457.16,622 532,621 R37.1@556,645
HARV_35: J36.2 R38.1 | length 74.8
  Bottom Layer w7: R38.1@686,890 723.49,852.51 J36.2@745.28,852.51
HARV_36: J37.2 R39.1 | length 85.9
  Bottom Layer w7: R39.1@1041,445 1041,413.87 1057.87,397 J37.2@1057.87,366.08
HARV_37: J38.2 R40.1 | length 108.1
  Top Layer w7: R40.1@755,-154 755,-93.32 J38.2@802.44,-93.32
HARV_38: J39.2 R41.1 | length 51.1
  Bottom Layer w7: R41.1@166,1110 185,1110 193.12,1101.88 J39.2@213.77,1101.88
HARV_39: J40.2 R42.1 | length 62
  Bottom Layer w7: J40.2@1112.09,-216.78 1115,-213.87 R42.1@1115,-156
HARV_40: J41.2 R43.1 | length 59.5
  Top Layer w7: J41.2@68.72,779.74 91,779.74 101.26,790 R43.1@124,790
HARV_41: J42.2 R44.1 | length 76.1
  Bottom Layer w7: J42.2@804.88,55 804.88,89 810,94.12 R44.1@810,129
HARV_42: J43.2 R45.1 | length 86.3
  Bottom Layer w7: R45.1@626,545 626,497.01 J43.2@653.12,469.89
HARV_43: J44.2 R46.1 | length 74.8
  Bottom Layer w7: R46.1@251,745 288.88,745 290.77,743.12 J44.2@324.99,743.12
HARV_44: J45.2 R47.1 | length 72.5
  Bottom Layer w7: R47.1@-149,765 -129.59,784.41 J45.2@-84.5,784.41
HARV_45: J46.2 R48.1 | length 145.3
  Top Layer w7: R48.1@940,-329 967.01,-329 1002.48,-364.46 J46.2@1070.64,-364.46
HARV_46: J47.2 R49.1 | length 84.9
  Top Layer w7: R49.1@1075,146 1097.42,168.42 J47.2@1097.42,221.57
HARV_47: J48.2 R50.1 | length 92.2
  Top Layer w7: J48.2@851.05,744.97 851.05,714.95 R50.1@895,671
HARV_48: J49.2 R51.1 | length 53.4
  Top Layer w7: J49.2@358.52,1066.17 382.68,1042 392,1042 R51.1@399,1035
HARV_49: J51.2 R56.1 | length 122.1
  Top Layer w7: J51.2@366.38,320.31 366.38,297 367.38,296 445,296 R56.1@459,310
HARV_IN: C3.+ R4.2 R5.2 R6.2 R7.2 R8.2 R9.2 R10.2 R11.2 R12.2 R13.2 R14.2 R15.2 R16.2 R17.2 R18.2 R19.2 R20.2 R21.2 R22.2 R23.2 R24.2 R25.2 R26.2 R27.2 R28.2 R29.2 R30.2 R31.2 R32.2 R33.2 R34.2 R35.2 R36.2 R37.2 R38.2 R39.2 R40.2 R41.2 R42.2 R43.2 R44.2 R45.2 R46.2 R47.2 R48.2 R49.2 R50.2 R51.2 R54.2 R56.2 TP1.1 | length 15654.6
  Top Layer w7: R31.2@-1115,-104 -1074.79,-63.79 v1(-1074.79,-2.21) ; R30.2@-1020,456 -954,522 v1(-954,575) ; v1(-899,-626) -899,-629.52 -906,-636.52 R12.2@-906,-670 -840,-604 v1(-785,-604) -580,-604 -565,-589 v1(-565,-565) ; R23.2@-796,-270 -762,-236 v1(-740,-236) ; R22.2@-785,181 -764.5,181 v1(-746.5,199) ; v1(-656,995) R29.2@-710,941 -673.32,904.32 -673.32,758.72 -653.1,738.5 -653.1,592.9 R21.2@-670,576 -632.5,576 v1(-613.5,595) ; R13.2@-466,-1035 -450,-1051 v1(-450,-1073) ; R20.2@-224,745 -173.72,795.28 -168.77,795.28 -155.55,808.5 v1(-153,808.5) ; v1(-210,-740) -207.51,-742.49 -202.51,-742.49 -191,-754 R5.2@-191,-775 -191,-804.69 v1(-169.88,-825.81) ; R28.2@-89,1105 -84,1110 v1(-44,1110) ; v1(0,-1115) 15,-1100 R14.2@104,-1100 ; v1(106.58,-1053.58) 106.58,-1057.09 104,-1059.67 R14.2@104,-1100 ; R43.2@166,790 v1(209,790) ; v1@244,-824 245,-823 245,-771 R6.2@244,-770 ; v1(245,-825) 245,-959 R14.2@104,-1100 ; R54.2@405,-326 474.5,-395.5 474.5,-405.5 ; v1(418.5,1003) 435.5,1020 436.9,1020 436.9,1030.9 R51.2@441,1035 ; TP1.1@435,-405 474,-405 474.5,-405.5 ; R56.2@501,310 494,317 494,336.42 488.5,341.92 488.5,373.5 v1(531.5,416.5) ; R37.2@514,645 532.9,645 537,649.1 537,659.02 567.98,690 v1(655,690) 681.09,663.91 681.09,653.6 704.69,630 v1(865,630) ; v1(555,-980) 555.5,-979.5 575.5,-979.5 659,-896 R15.2@659,-875 659,-766.79 663.72,-762.08 663.72,-600.14 602.07,-538.49 584.17,-538.49 v1(581.68,-536) 581.68,-512.68 R7.2@544,-475 474.5,-405.5 ; v1(765.38,190.27) 761.86,190.27 757.12,185.53 755.13,185.53 729.98,160.37 729.98,34.79 736,28.77 736,-168.02 740.98,-173 750.9,-173 755,-177.1 R40.2@755,-196 v1(818,-259) ; R36.2@808.33,305.88 830,284.22 843.39,284.22 858.06,269.56 858.06,185.07 855,182.02 v1(855,178.5) ; v1@866,629 867,630 894,630 R50.2@895,629 ; R48.2@940,-371 940,-411.29 947,-418.29 v1(947,-421.81) ; R49.2@1075,104 1075,36.76 1115,-3.24 v1(1115,-67)
  Int1 (PWR) w7: v1(-1012,-489) -1012,-545.08 -931.08,-626 v1(-899,-626) ; v1(-656,995) -474.55,995 -359.55,1110 v1(-44,1110) ; v1(-389,-551) -354.92,-585.08 -345.51,-585.08 -251.09,-679.5 -251.09,-698.9 v1(-250,-700) ; v1(-169.88,-825.81) -169.48,-825.4 244.6,-825.4 v1(245,-825) ; v1(-153,808.5) 10.51,808.5 18.01,816 183,816 v1(209,790) 247.5,828.5 491.5,828.5 510,810 535,810 v1(655,690) ; v1(106.58,-1053.58) 107.87,-1052.29 474.71,-1052.29 v1(476,-1051) ; v1(152.5,1059.19) 362.31,1059.19 v1(418.5,1003) ; v1(818,-259) 1010,-67 v1(1115,-67)
  Int2 (GND) w7: v1(-785,-604) -767.46,-586.46 -767.46,-263.46 -737.51,-233.51 -720.94,-233.51 -664,-176.58 -664,116.5 v1(-746.5,199) ; v1(-577,-887) -577,-946 v1(-450,-1073) ; v1(-139.28,726.11) -139.28,694.87 -144.5,689.65 -144.5,654.7 -136.06,646.26 -136.06,546.37 -145.5,536.92 -145.5,536.32 -156.92,524.89 -157.53,524.89 -258,424.42 -258,389.68 -288.51,359.17 -288.51,278.51 -200.5,190.5 -190.5,190.5 v2(-100,100) ; v1(531.5,416.5) 573.67,458.67 655,540 v1(655,690) ; v1(765.38,190.27) 781.23,206.12 781.23,293.68 929.27,441.73 940.01,441.73 951.43,453.15 951.43,463.89 952.54,465 952.54,555.27 916.42,591.39 903.61,591.39 v1(865,630) ; v1(818,-259) 874.5,-315.5 874.5,-571.5 903,-600 v1(905,-600) 907.45,-597.55 907.45,-461.35 v1(947,-421.81)
  Bottom Layer w7: v1(-1074.79,-2.21) -1074.79,34.05 -1095,54.26 R34.2@-1095,94 -990,199 R25.2@-780,199 v1(-746.5,199) ; R35.2@-1015,-451 -1012,-454 v1(-1012,-489) ; v1(-954,575) R33.2@-910,619 -886,595 v1(-613.5,595) R24.2@-575,595 ; R26.2@-760,-186 -760,-216 v1(-740,-236) ; v1(-656,995) R32.2@-456,995 ; v1(-577,-887) R16.2@-604,-860 -604,-604 v1(-565,-565) -564,-565 R27.2@-550,-551 v1(-389,-551) ; v1(-250,-700) -247.51,-702.49 -247.51,-706.49 R8.2@-234,-720 -216.49,-737.51 -212.49,-737.51 v1(-210,-740) ; C3.+@-180,113.98 -166.02,100 v2(-100,100) ; v1(-153,808.5) -153,807.95 -167.22,793.73 -167.22,788.78 R47.2@-191,765 -154.6,728.6 -141.76,728.6 v1(-139.28,726.11) ; R17.2@-94,-1115 v1(0,-1115) ; v1(-44,1110) R41.2@124,1110 124,1087.69 ; v1(152.5,1059.19) 124,1087.69 ; R9.2@206,-775 242.51,-811.51 242.51,-822.51 v1(245,-825) ; R46.2@209,745 v1(209,790) 209,915 124,1000 124,1087.69 ; v1(476,-1051) 473.51,-1048.51 473.51,-1042.51 R18.2@456,-1025 510,-1025 v1(555,-980) ; v1(581.68,-536) R10.2@550.73,-566.95 612.78,-629 R19.2@885,-629 902.51,-611.49 902.51,-602.49 v1(905,-600) ; R45.2@584,545 634.5,595.5 634.5,672 652.5,690 v1(655,690) 655,693.52 644,704.52 R38.2@644,890 ; R11.2@755,-234 793,-234 v1(818,-259) ; v1(765.38,190.27) 766.73,191.62 789.38,191.62 R44.2@810,171 825,186 843.98,186 851.48,178.5 v1(855,178.5) ; v1(865,630) 893.96,601.04 906.77,601.04 1000,507.81 1000,446 R39.2@999,445 ; R42.2@1115,-114 v1(1115,-67)
HARV_VOLT: C30.2 R54.1 R55.2 U5.18 | length 240
  Top Layer w7: U5.18@404.55,-182.1 404.55,-250 ; R54.1@405,-284 404.55,-283.55 404.55,-250 ; R55.2@445,-284 445,-260 440,-255 ; C30.2@485,-284 485,-263 477,-255 440,-255 ; 404.55,-250 409.55,-255 440,-255
JTAG_TCK: J53.3 U2.25 | length 562.1
  Top Layer w7: J53.3@-75,-15 -115,-15 -128.89,-1.11 -128.89,141.11 -73.55,196.45 -73.43,196.45 -36.29,233.58 -36.29,233.71 19.68,289.68 19.68,311.48 v1(51.7,343.5)
  Bottom Layer w7: v1(51.7,343.5) 51.7,364.3 62.71,375.31 103.97,375.31 105.1,374.17 U2.25@105.1,370.39
JTAG_TDI: J53.5 U2.27 | length 850.8
  Top Layer w7: J53.5@-89.88,-90.07 -144.93,-90.07 -155,-80 -155,148.94 -83.49,220.45 -83.37,220.45 -60.29,243.53 -60.29,243.65 -58,245.94 -58,298.48 35.03,391.5 35.03,408.47 59.55,433 92.25,433 v1(123.67,464.41)
  Bottom Layer w7: v1(123.67,464.41) 124.94,463.14 124.94,406.15 144.74,386.35 U2.27@144.74,370.67
JTAG_TDO: J53.4 U2.26 | length 679.4
  Top Layer w7: J53.4@-75,-50 -130,-50 -140.89,-39.11 -140.89,146.08 -78.52,208.45 -78.4,208.45 -48.29,238.56 -48.29,238.68 -45.48,241.49 -45.48,282.48 43.85,371.8 43.85,380.87 54.53,391.55 v1(54.53,395.07)
  Bottom Layer w7: v1(54.53,395.07) 75.79,395.07 78.53,397.8 116.32,397.8 124.78,389.33 U2.26@124.78,370.39
JTAG_TMS: J53.2 U2.24 | length 559.9
  Top Layer w7: J53.2@-100,30 55,30 89.2,64.2 89.2,120.8 31.68,178.32 31.68,291.47 83.3,343.09 96.2,343.09 v1(97.24,344.13)
  Bottom Layer w7: U2.24@79.51,344.8 79.85,344.47 96.91,344.47 v1(97.24,344.13)
MUXA1: J2.6 U4.19 | length 371.5
  Top Layer w7: J2.6@-365.39,-683.06 -341.31,-658.98 -341.31,-619.88 -334.09,-612.66 -334.09,-610.5 -281.66,-558.08 -281.66,-541.66 -180,-440 -175,-440 -172.99,-442.01 -172.99,-443.63 v1(-174.43,-443.63)
  Bottom Layer w7: v1(-174.43,-443.63) -173.93,-443.14 -173.48,-443.14 -173.48,-404.27 U4.19@-173.98,-403.78
MUXA2: J3.6 U4.20 | length 619.5
  Top Layer w7: v1(10.97,-714.8) 12.44,-716.27 24.36,-716.27 28.46,-720.37 J3.6@28.46,-785.89
  Int2 (GND) w7: v1(-128.91,-488) -128.91,-571.06 -167.89,-610.03 -167.89,-670.15 -167.35,-670.69 -167.35,-686.84 -167.89,-687.38 -167.89,-689.58 -156.46,-701 -139.77,-701 -134.17,-695.4 -79.46,-695.4 -59.32,-715.53 -59.32,-722.72 -47.9,-734.14 -40.72,-734.14 -11.66,-734.14 7.69,-714.8 v1(10.97,-714.8)
  Bottom Layer w7: U4.20@-148.39,-403.78 -148.39,-429.92 -154.93,-436.46 -154.93,-452.61 -148.39,-459.15 -148.39,-468.53 -130.98,-485.93 -130.98,-490.07 v1(-128.91,-488)
MUXA3: J4.6 U4.21 | length 749.2
  Top Layer w7: v1(375,-581.5) 377.49,-583.99 377.49,-599.73 431.71,-653.95 J4.6@431.71,-677.95
  Int1 (PWR) w7: v1(-65,-543.61) -27.11,-581.5 86.95,-581.5 91.95,-586.5 118.05,-586.5 123.05,-581.5 v1(375,-581.5)
  Bottom Layer w7: U4.21@-122.8,-403.78 -122.8,-429.59 -115.93,-436.46 -115.93,-452.61 -122.8,-459.48 -122.8,-466.54 -66.22,-523.11 -66.22,-542.39 v1(-65,-543.61)
MUXA4: J5.6 U4.22 | length 970.7
  Top Layer w7: v1(-45,-525) -7.79,-525 14.16,-503.05 v1(37.89,-503.05) ; v1(590,-380) 609.32,-360.68 621.8,-360.68 632.81,-349.66 638.33,-349.66 654.64,-365.97 J5.6@681.92,-365.97
  Int1 (PWR) w7: v1(37.89,-503.05) 54.85,-520 455.96,-520 537.67,-438.28 537.67,-425.45 559.15,-403.97 566.03,-403.97 v1(590,-380)
  Bottom Layer w7: U4.22@-97.2,-403.78 -97.2,-472.8 v1(-45,-525)
MUXA5: J6.6 U4.23 | length 661.7
  Top Layer w7: v1(-379.09,-593.18) -362.77,-576.87 -357.23,-576.87 -343.41,-563.05 -343.41,-543.35 v1(-342.61,-542.55)
  Bottom Layer w7: v1(-379.09,-593.18) -376.6,-595.67 -376.6,-610.31 J6.6@-372.36,-614.55 ; v1(-342.61,-542.55) -340.12,-540.06 -340.12,-522.54 -318.08,-500.5 -301.92,-500.5 -286.08,-516.34 -286.08,-560.6 -270.24,-576.44 -68.86,-576.44 -25.5,-533.08 -25.5,-501.69 -71.61,-455.57 U4.23@-71.61,-403.78
MUXA6: J7.6 U4.24 | length 616.1
  Int2 (GND) w7: v1(31.08,-557.75) 34.6,-557.75 42.04,-565.19 48.07,-565.19 53.54,-570.67 53.54,-591.9 v1(86.47,-624.83)
  Bottom Layer w7: U4.24@-46.02,-403.78 -46.02,-421.5 -24.3,-443.22 -24.3,-468.43 39.58,-532.31 39.58,-545.74 31.08,-554.24 v1(31.08,-557.75) ; J7.6@-20.32,-785.53 -20.32,-746.14 -31.79,-734.67 -40.09,-734.67 -50.28,-724.48 -50.28,-700.28 -45,-695 -40.61,-695 -38.99,-693.37 -33.75,-693.37 -33.63,-693.25 -22.71,-693.25 -22.66,-693.3 -12.08,-693.3 -2.08,-683.3 24.02,-683.3 44.72,-704 75.02,-704 79.12,-699.9 79.12,-670.96 79.28,-670.81 79.28,-654.65 79.12,-654.5 79.12,-635.43 86.47,-628.08 v1(86.47,-624.83)
MUXA7: J8.6 U4.25 | length 967.1
  Int1 (PWR) w7: v1(-4.8,-442.11) -4.8,-504.9 28.55,-538.25 39.16,-538.25 44.9,-544 66.42,-544 96.92,-574.5 113.08,-574.5 125.58,-562 467.33,-562 v1(527.15,-502.18)
  Bottom Layer w7: U4.25@-20.43,-403.78 -20.43,-423.33 -4.8,-438.97 v1(-4.8,-442.11) ; J8.6@394.67,-701.65 381.06,-688.04 381.06,-651.33 390.96,-641.43 390.96,-632.95 519.24,-504.67 524.66,-504.67 v1(527.15,-502.18)
MUXA8: J9.6 U4.26 | length 962.6
  Int1 (PWR) w7: v1(-22.74,-336.77) 4.52,-309.5 112.01,-309.5 113.01,-308.5 309.53,-308.5 318.03,-300 v1(610,-300)
  Bottom Layer w7: v1(-22.74,-336.77) 5.16,-364.67 U4.26@5.16,-403.78 ; v1(610,-300) 582.79,-327.21 566.14,-327.21 546.42,-346.92 546.42,-364 581.92,-399.5 599.6,-399.5 606.64,-392.46 641.69,-392.46 J9.6@657.99,-408.76
MUXA9: J10.6 U4.11 | length 724.6
  Top Layer w7: J10.6@-770.05,-807.24 -770.05,-792.85 -729.73,-752.53 -729.73,-745.92 -719.12,-735.32 -719.12,-733.59 -701.79,-716.27 v1(-699.45,-716.27)
  Int1 (PWR) w7: v1(-699.45,-716.27) -697.08,-713.9 -480.31,-713.9 -470.7,-723.5 -469.08,-723.5 -458.08,-734.5 -441.92,-734.5 -430.92,-723.5 -244.5,-723.5 -211.72,-690.72 -202.32,-690.72 -190.37,-678.77 v1(-186.85,-678.77)
  Bottom Layer w7: U4.11@-199.57,-626.22 -199.57,-662.53 -186.85,-675.25 v1(-186.85,-678.77)
MUXA10: J11.6 U4.10 | length 553.6
  Top Layer w7: J11.6@-265.24,-1084.01 v1(-265.24,-800)
  Bottom Layer w7: v1(-265.24,-800) -175.6,-800 -171.5,-795.9 -171.5,-691 -167.35,-686.84 -167.35,-670.69 -173.98,-664.06 U4.10@-173.98,-626.22
MUXA11: J12.6 U4.9 | length 910.3
  Top Layer w7: J12.6@317.68,-1076.11 317.68,-1001.32 v1(372,-947)
  Int2 (GND) w7: v1(-147.85,-681.5) -148.17,-681.17 -148.17,-657.5 -135,-644.33 -36.15,-644.33 -34.12,-642.3 64.87,-642.3 66.9,-644.33 114.33,-644.33 372,-902 v1(372,-947)
  Bottom Layer w7: U4.9@-148.39,-626.22 -148.12,-626.49 -148.12,-681.23 v1(-147.85,-681.5)
MUXA12: J13.6 U4.8 | length 1222.6
  Top Layer w7: v1(719,-915) 735,-899 777.08,-899 845,-831.07 845,-803.85 J13.6@810,-768.85
  Int1 (PWR) w7: v1(-119,-667) -12.5,-773.5 59.04,-773.5 69.54,-784 173.51,-784 176.01,-781.5 537.46,-781.5 571.27,-815.3 619.3,-815.3 v1(719,-915)
  Bottom Layer w7: U4.8@-122.8,-626.22 -122.8,-663.2 v1(-119,-667)
MUXA13: J14.6 U4.7 | length 859.6
  Int1 (PWR) w7: v1(-740.97,-729.42) -740.86,-729.42 -710.78,-759.5 -583.08,-759.5 -573.08,-769.5 -556.92,-769.5 -546.92,-759.5 -201.92,-759.5 -191.14,-748.72 -126.3,-748.72 v1(-125.15,-747.57)
  Bottom Layer w7: J14.6@-805.86,-770.76 -790.13,-770.76 -751.29,-731.91 -743.46,-731.91 v1(-740.97,-729.42) ; v1(-125.15,-747.57) -121.63,-747.57 -111.79,-737.73 -110.95,-737.73 -106,-732.78 -106,-697.5 -96.5,-688 -96.5,-661.2 -97.2,-660.5 U4.7@-97.2,-626.22
MUXA14: J15.6 U4.6 | length 586.4
  Bottom Layer w7: J15.6@-311.98,-1071.09 -309.6,-1068.72 -309.6,-1017.98 -319.5,-1008.08 -319.5,-979.5 -256.12,-916.12 -200.7,-916.12 -113.08,-828.5 -110.92,-828.5 -94,-811.58 -94,-717.63 -71.61,-695.25 U4.6@-71.61,-626.22
MUXA15: J16.6 U4.5 | length 716.1
  Int2 (GND) w7: v1(-46.4,-667.91) -42.88,-667.91 -29.27,-654.3 -13,-654.3 -8.54,-658.75 -1.35,-658.75 285.9,-946 v1(303,-946)
  Bottom Layer w7: v1(-46.4,-667.91) -46.21,-667.72 -46.21,-626.41 U4.5@-46.02,-626.22 ; J16.6@265.31,-1089.48 265.31,-1065.91 226.31,-1026.91 226.31,-1010.75 288.58,-948.49 300.51,-948.49 v1(303,-946)
MUXA16: J17.6 U4.4 | length 911
  Int1 (PWR) w7: v1(-21.08,-673.8) 13.7,-673.8 84.9,-745 575.73,-745 585.92,-734.81 625.03,-734.81 v1(644.22,-754)
  Bottom Layer w7: v1(-21.08,-673.8) -20.43,-643.94 U4.4@-20.43,-626.22 ; v1(644.22,-754) 644.22,-760 663.22,-779 747.68,-779 J17.6@775.34,-806.66
MUXA17: J18.6 U7.19 | length 813.5
  Top Layer w7: J18.6@-420.47,650.55 -420.47,638.05 -380.86,598.43 -380.86,584.14 v1(-381.06,583.94)
  Int2 (GND) w7: v1(-562.9,71.48) -562.9,109.52 -540.5,131.92 -540.5,238.79 -519,260.29 -519,369.5 -382,506.5 -382,583 v1(-381.06,583.94)
  Bottom Layer w7: v1(-562.9,71.48) -540.42,49 -475.52,49 -465.5,38.98 U7.19@-433.78,38.98
MUXA18: J19.6 U7.20 | length 1420.7
  Top Layer w7: J19.6@-699.66,368.06 -676.58,368.06 -633.52,325 -630,325 -628.71,325 v1(-616.71,325)
  Int1 (PWR) w7: v1(-616.71,325) -623.36,331.64 -612.5,342.5 -547.95,342.5 -410.5,205.05 -410.5,-345 v1(-376,-379.5)
  Bottom Layer w7: U7.20@-433.78,13.39 -398.67,13.39 -376,-9.29 v1(-376,-379.5)
MUXA19: J20.6 U7.21 | length 399
  Top Layer w7: J20.6@-792.57,-38.24 -785.26,-45.55 v1(-723.71,-45.55)
  Int1 (PWR) w7: v1(-723.71,-45.55) -721.22,-48.04 -705.49,-48.04 -703.67,-49.87 -687.51,-49.87 -683.2,-45.55 -609.37,-45.55 -601.02,-37.2 -597.5,-37.2 -597.29,-37.2 v1(-595.41,-35.32)
  Bottom Layer w7: v1(-595.41,-35.32) -595.41,-37.2 -564.44,-37.2 -533.77,-6.53 -504.23,-6.53 -494.5,-16.26 -494.5,-18.08 -486.7,-25.87 -463.3,-25.87 -455.5,-18.08 ; -455.5,-18.04 -449.66,-12.2 U7.21@-433.78,-12.2
MUXA20: J21.6 U7.22 | length 548.2
  Top Layer w7: J21.6@-623.8,-416.65 -608.65,-416.65 v1(-517,-325)
  Int1 (PWR) w7: v1(-517,-325) -522,-320 -522,-135.5 v1(-517,-130.5)
  Bottom Layer w7: v1(-517,-130.5) -549.5,-98 -549.5,-66.92 -528.11,-45.53 -492.88,-45.53 -485.23,-37.87 -433.86,-37.87 U7.22@-433.78,-37.79
MUXA21: J22.6 U7.23 | length 1151
  Int2 (GND) w7: v1(-471.44,-69.2) -455.5,-53.26 -455.5,181.47 -363.5,273.47 -363.5,376.5 -330,410 -330,559.5 -289.5,600 v1(-289.5,708)
  Bottom Layer w7: v1(-471.44,-69.2) -467.93,-69.2 -463.41,-64.68 -435.08,-64.68 U7.23@-433.78,-63.39 ; J22.6@-376.45,676.99 -396,721.19 -396,752.5 -377.5,771 -297.5,771 -282,755.5 -282,715.5 v1(-289.5,708)
MUXA22: J23.6 U7.24 | length 1161
  Int1 (PWR) w7: v1(-565.71,323) -545.42,323 -423,200.58 -423,-240.58 -468.33,-285.9 -488.4,-285.9 v1(-488.83,-286.33)
  Bottom Layer w7: J23.6@-672.52,409.48 -621.92,395.12 -603.3,388.31 cw(c-610,370) -592.56,378.72 -565.71,351.87 v1(-565.71,323) ; v1(-488.83,-286.33) -488.83,-251.25 -472.9,-235.32 -438.28,-235.32 -400,-197.04 -400,-89.98 -401,-88.98 U7.24@-433.78,-88.98
MUXA23: J24.6 U7.25 | length 835.8
  Bottom Layer w7: J24.6@-794.88,15 -860.3,15 -879.7,-4.39 -879.7,-92.73 -825.5,-146.92 -825.5,-200.46 -830,-204.96 -830,-260.9 -825.9,-265 -616.3,-265 -506.5,-155.2 -506.5,-151.95 -488.05,-133.5 -484.8,-133.5 -465.87,-114.57 U7.25@-433.78,-114.57
MUXA24: J25.6 U7.26 | length 349
  Bottom Layer w7: J25.6@-648.12,-373.29 -645.86,-373.29 -609.29,-336.71 -609.29,-334.46 -590,-315.17 -590,-310 -541,-261 -541,-206.67 -494.5,-160.17 -494.5,-156.92 -483.08,-145.5 -479.83,-145.5 -474.49,-140.16 U7.26@-433.78,-140.16
MUXA25: J26.6 U7.11 | length 1222.1
  Top Layer w7: v1(-342,960) -311.57,990.43 J26.6@-311.57,1078.54
  Int2 (GND) w7: v1(-581.34,211.34) -581.34,280.62 -585.21,284.49 -585.21,350.24 -539.5,395.95 -539.5,575.5 -342,773 v1(-342,960)
  Bottom Layer w7: U7.11@-656.22,64.57 -618.01,64.57 -584.33,98.24 -574.18,98.24 -540.5,131.92 -540.5,149.45 -575,183.95 -575,187.34 -578.86,191.2 -578.86,208.86 v1(-581.34,211.34)
MUXA26: J27.6 U7.10 | length 852.6
  Top Layer w7: J27.6@-806.12,775.62 v1(-729,698.5)
  Int2 (GND) w7: v1(-729,698.5) -781.5,646 -781.5,146.5 v1(-705,70)
  Bottom Layer w7: v1(-705,70) -673.96,38.98 U7.10@-656.22,38.98
MUXA27: J28.6 U7.9 | length 665.5
  Top Layer w7: J28.6@-1084.06,265.14 -1014.42,265.14 v1(-876,126.72)
  Int1 (PWR) w7: v1(-876,126.72) -770.28,21 -726.58,21 -723.08,24.5 -706.92,24.5 -703.42,21 v1(-591,21)
  Bottom Layer w7: U7.9@-656.22,13.39 -598.61,13.39 v1(-591,21)
MUXA28: J29.6 U7.8 | length 676.7
  Top Layer w7: J29.6@-1071.14,-318.4 -1057.74,-305 -940.5,-305 -930,-294.5 v1(-930,-265)
  Int2 (GND) w7: v1(-930,-265) -930,-180.5 -857.57,-108.07 -686.57,-108.07 -676,-97.5 -676,-48 -693.63,-30.37 v1(-695.59,-30.37)
  Bottom Layer w7: v1(-695.59,-30.37) -693.84,-30.37 -675.68,-12.2 U7.8@-656.22,-12.2
MUXA29: J30.6 U7.7 | length 1944.1
  Int2 (GND) w7: v1(-568.34,-61.87) -596.44,-61.87 -628,-30.31 -628,176.53 -648.21,196.74 -648.21,587.86 -611.5,624.58 -611.5,669.54 -621.5,679.54 -621.5,958.5 -530.87,1049.13 -530.87,1095.54 -462.36,1164.06 -408.52,1164.06 -362.58,1210 -280,1210 -249,1179 -249,1040.88 -235.6,1027.48 v1(-235.6,1025.29)
  Bottom Layer w7: U7.7@-656.22,-37.79 -630.71,-37.79 -608,-60.5 -569.71,-60.5 v1(-568.34,-61.87) ; J30.6@-265.12,1094.08 -265.12,1060.06 -238.08,1033.02 -238.08,1027.78 v1(-235.6,1025.29)
MUXA30: J31.6 U7.6 | length 1175.5
  Int2 (GND) w7: v1(-699,-76) -778,-76 -794,-60 -794,777.5 -786.37,785.13 v1(-696.19,785.13)
  Bottom Layer w7: J31.6@-770.67,811.03 -742.14,782.49 -702.35,782.49 -699.7,785.13 v1(-696.19,785.13) ; v1(-699,-76) -686.39,-63.39 U7.6@-656.22,-63.39
MUXA31: J32.6 U7.5 | length 856.2
  Int1 (PWR) w7: v1(-962.15,325.28) -975.48,311.95 -975.48,87.91 -767.58,-120 -625.77,-120 -621.36,-124.42 v1(-617.84,-124.42)
  Bottom Layer w7: J32.6@-1066.14,313.45 -1013.61,310.85 v1(-962.15,325.28) ; U7.5@-656.22,-88.98 -638.5,-88.98 -620.33,-107.15 -620.33,-121.93 v1(-617.84,-124.42)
